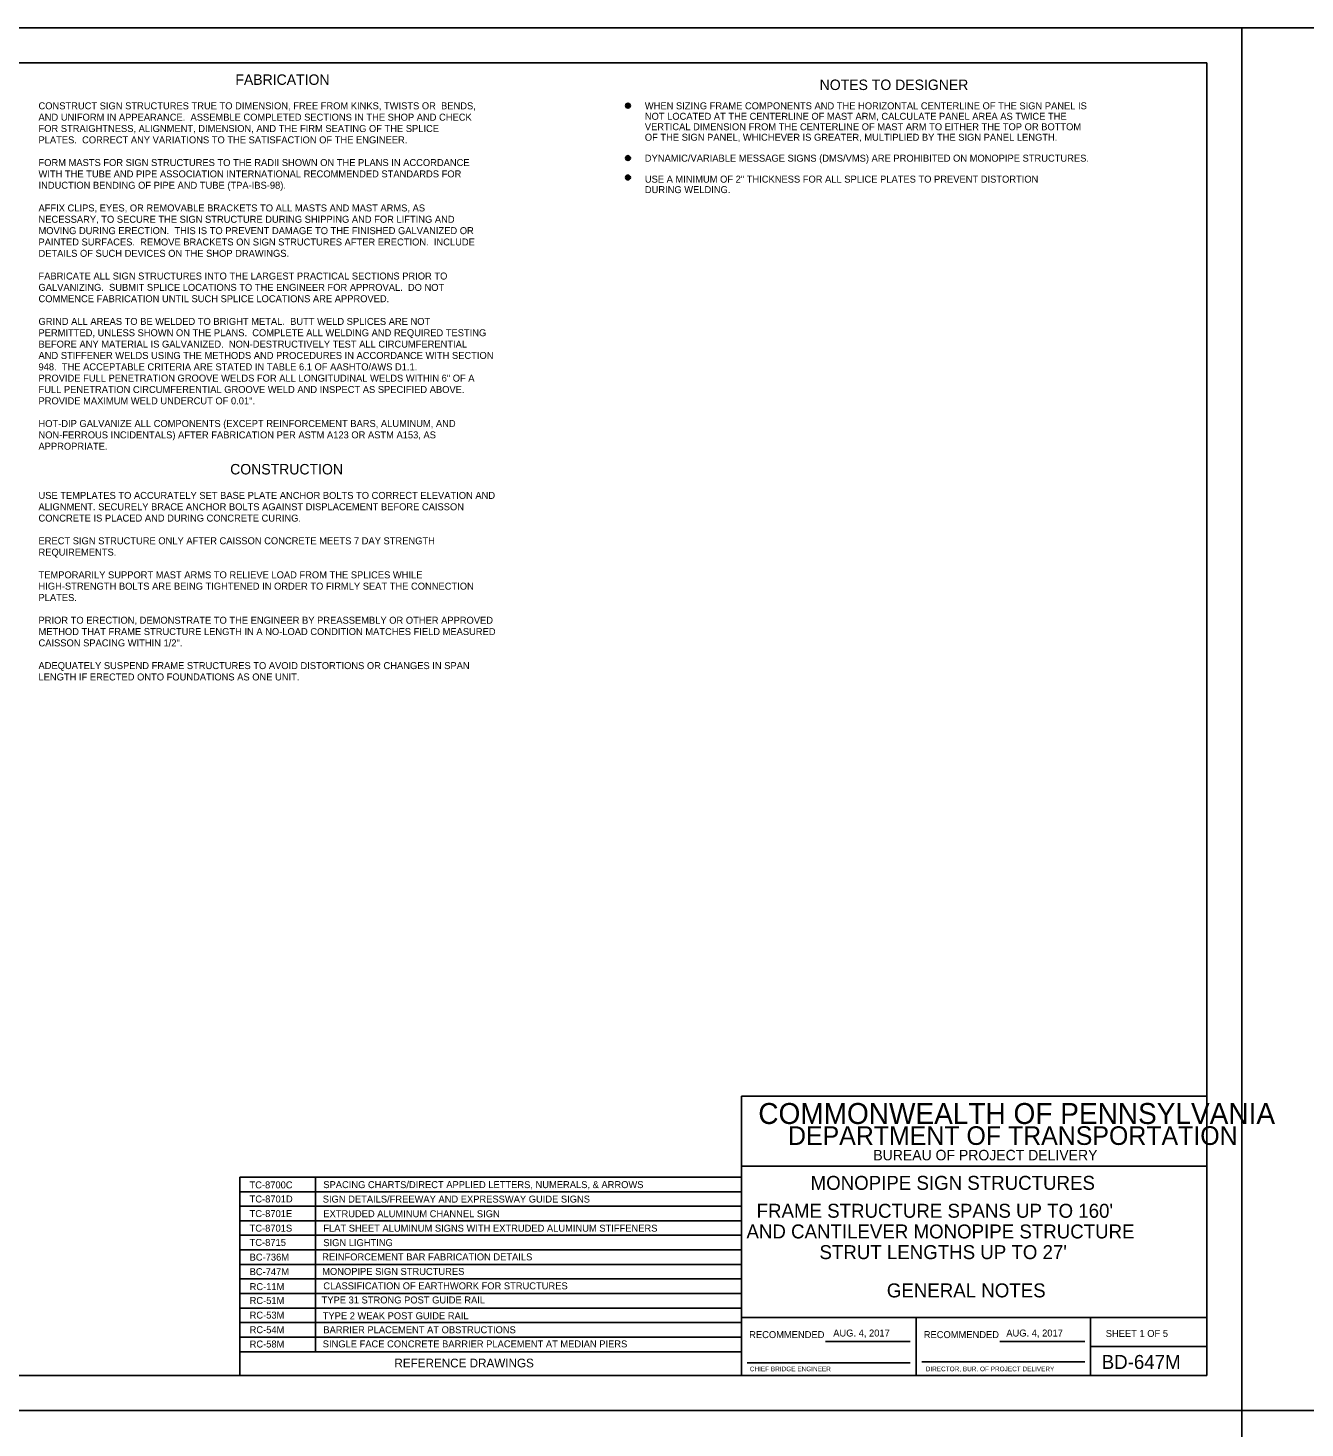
# Model space of a CAD drawing. Extents: x 640117 to 642655, y 297247 to 298435.
# Drawn here: x 640437 to 640986, y 297834 to 298435 of the extents above; entities that cross this region are included whole.
import ezdxf

# ---------------------------------------------------------------- set-up
doc = ezdxf.new("R2010")
doc.units = 0
for name, color, linetype in [('1', 7, 'Continuous'), ('10', 7, 'Continuous'), ('13', 7, 'Continuous'), ('2', 7, 'Continuous'), ('52', 7, 'Continuous'), ('53', 7, 'Continuous'), ('PLT-BNDY', 7, 'Continuous')]:
    doc.layers.add(name, color=color, linetype=linetype)

msp = doc.modelspace()

# ---------------------------------------------------------------- linework, layer by layer
at = {"layer": '1'}
for p, q in [((640818.46, 297856.46), (640818.46, 297881.46)), ((640779.54, 297871.17), (640815.96, 297871.17)), ((640854.54, 297871.17), (640890.96, 297871.17)), ((640745.96, 297861.96), (640815.96, 297861.96)), ((640820.96, 297862.33), (640890.96, 297862.33))]:
    msp.add_line(p, q, dxfattribs=at)
at = {"layer": '10'}
for centre, radius in [((640694.7, 298402.07), 1.04), ((640694.7, 298402.07), 0.781), ((640694.7, 298402.07), 0.521), ((640694.7, 298402.07), 0.26), ((640694.7, 298402.07), 0.00000208), ((640694.7, 298379.57), 1.04), ((640694.7, 298379.57), 0.781), ((640694.7, 298379.57), 0.521), ((640694.7, 298379.57), 0.26), ((640694.7, 298379.57), 0.00000208), ((640694.7, 298371.21), 1.04), ((640694.7, 298371.21), 0.781), ((640694.7, 298371.21), 0.521), ((640694.7, 298371.21), 0.26), ((640694.7, 298371.21), 0.00000208)]:
    msp.add_circle(centre, radius, dxfattribs=at)
at = {"layer": '13'}
for p, q in [((640528, 297856.46), (640528, 297941.74)), ((640528, 297941.74), (640743.46, 297941.74)), ((640560.46, 297866.74), (640560.46, 297941.74)), ((640528, 297935.49), (640743.46, 297935.49)), ((640528, 297929.24), (640743.46, 297929.24)), ((640528, 297922.99), (640743.46, 297922.99)), ((640528, 297916.74), (640743.46, 297916.74)), ((640528, 297910.49), (640743.46, 297910.49)), ((640528, 297904.24), (640743.46, 297904.24)), ((640528, 297897.99), (640743.46, 297897.99)), ((640528, 297891.74), (640743.46, 297891.74)), ((640528, 297885.49), (640743.46, 297885.49)), ((640528, 297879.24), (640743.46, 297879.24)), ((640528, 297872.99), (640743.46, 297872.99)), ((640528, 297872.99), (640743.46, 297872.99)), ((640528, 297866.74), (640743.46, 297866.74))]:
    msp.add_line(p, q, dxfattribs=at)
at = {"layer": '2'}
for p, q in [((640157.46, 298420.46), (640943.46, 298420.46)), ((640943.46, 298420.46), (640943.46, 297856.46)), ((640943.46, 297976.46), (640743.46, 297976.46)), ((640743.46, 297976.46), (640743.46, 297856.46)), ((640943.46, 297856.46), (640943.46, 297976.46)), ((640943.46, 297946.46), (640743.46, 297946.46)), ((640943.46, 297881.46), (640743.46, 297881.46)), ((640893.46, 297881.46), (640893.46, 297856.46)), ((640893.46, 297868.96), (640943.46, 297868.96)), ((640943.46, 297856.46), (640157.46, 297856.46)), ((640743.46, 297856.46), (640943.46, 297856.46))]:
    msp.add_line(p, q, dxfattribs=at)
at = {"layer": 'PLT-BNDY'}
for points in [[(640117.46, 298435.46), (640958.46, 298435.46), (640958.46, 297841.46), (640117.46, 297841.46)], [(640958.46, 298435.46), (641799.46, 298435.46), (641799.46, 297841.46), (640958.46, 297841.46)], [(640117.46, 297841.46), (640958.46, 297841.46), (640958.46, 297247.46), (640117.46, 297247.46)], [(640958.46, 297841.46), (641799.46, 297841.46), (641799.46, 297247.46), (640958.46, 297247.46)]]:
    msp.add_lwpolyline(points, close=True, dxfattribs=at)

# ---------------------------------------------------------------- texts
at = {"layer": '1'}
for s, height, p in [('RECOMMENDED', 3, (640746.79, 297872.58)), ('RECOMMENDED', 3, (640821.79, 297872.58)), ('CHIEF BRIDGE ENGINEER', 2.0002, (640747.05, 297858.33)), ('DIRECTOR, BUR. OF PROJECT DELIVERY', 2.0002, (640822.63, 297858.33))]:
    msp.add_text(s, height=height, dxfattribs=at).set_placement(p)
at = {"layer": '10'}
for s, height, p in [('WHEN SIZING FRAME COMPONENTS AND THE HORIZONTAL CENTERLINE OF THE SIGN PANEL IS ', 3, (640701.96, 298400.52)), ('NOT LOCATED AT THE CENTERLINE OF MAST ARM, CALCULATE PANEL AREA AS TWICE THE ', 3, (640701.96, 298396.02)), ('VERTICAL DIMENSION FROM THE CENTERLINE OF MAST ARM TO EITHER THE TOP OR BOTTOM ', 3, (640701.96, 298391.52)), ('OF THE SIGN PANEL, WHICHEVER IS GREATER, MULTIPLIED BY THE SIGN PANEL LENGTH.', 3, (640701.96, 298387.02)), ('DYNAMIC/VARIABLE MESSAGE SIGNS (DMS/VMS) ARE PROHIBITED ON MONOPIPE STRUCTURES.', 3, (640701.96, 298378.02)), ('USE A MINIMUM OF 2" THICKNESS FOR ALL SPLICE PLATES TO PREVENT DISTORTION ', 3, (640701.96, 298369.02)), ('DURING WELDING. ', 3, (640701.96, 298364.52)), ('MONOPIPE SIGN STRUCTURES', 6, (640773.18, 297936.28)), ('TC-8700C', 3, (640532.11, 297936.9)), ('SPACING CHARTS/DIRECT APPLIED LETTERS, NUMERALS, & ARROWS', 3, (640563.83, 297937.02)), ('TC-8701D', 3, (640532.16, 297930.85)), ('SIGN DETAILS/FREEWAY AND EXPRESSWAY GUIDE SIGNS', 3, (640563.58, 297930.81)), ("FRAME STRUCTURE SPANS UP TO 160'", 6, (640749.98, 297924.28)), ('TC-8701E', 3, (640532.16, 297924.58)), ('EXTRUDED ALUMINUM CHANNEL SIGN', 3, (640563.83, 297924.51)), ('TC-8701S', 3, (640532.16, 297918.31)), ('FLAT SHEET ALUMINUM SIGNS WITH EXTRUDED ALUMINUM STIFFENERS', 3, (640563.83, 297918.3)), ('AND CANTILEVER MONOPIPE STRUCTURE', 6, (640745.61, 297915.4)), ('TC-8715', 3, (640532.16, 297912.19)), ('SIGN LIGHTING', 3, (640563.83, 297912.1)), ("STRUT LENGTHS UP TO 27'", 6, (640776.98, 297906.51)), ('BC-736M', 3, (640532.16, 297905.87)), ('REINFORCEMENT BAR FABRICATION DETAILS', 3, (640563.34, 297905.98)), ('BC-747M', 3, (640532.16, 297899.62)), ('MONOPIPE SIGN STRUCTURES', 3, (640563.34, 297899.73)), ('RC-11M', 3, (640532.16, 297893.2)), ('CLASSIFICATION OF EARTHWORK FOR STRUCTURES', 3, (640563.83, 297893.52)), ('GENERAL NOTES', 6, (640805.92, 297890.07)), ('RC-51M', 3, (640532.16, 297887.23)), ('TYPE 31 STRONG POST GUIDE RAIL', 3, (640563.09, 297887.46)), ('RC-53M', 3, (640532.16, 297880.96)), ('TYPE 2 WEAK POST GUIDE RAIL', 3, (640563.58, 297880.67)), ('RC-54M', 3, (640532.16, 297874.68)), ('BARRIER PLACEMENT AT OBSTRUCTIONS', 3, (640563.83, 297874.66)), ('RC-58M', 3, (640532.16, 297868.54)), ('SINGLE FACE CONCRETE BARRIER PLACEMENT AT MEDIAN PIERS', 3, (640563.58, 297868.59)), ('REFERENCE DRAWINGS', 3.75, (640594.37, 297859.99)), ('BD-647M', 6, (640898.25, 297859.33))]:
    msp.add_text(s, height=height, dxfattribs=at).set_placement(p)
at = {"layer": '2'}
for s, height, p in [('COMMONWEALTH OF PENNSYLVANIA', 9, (640750.71, 297964.58)), ('DEPARTMENT OF TRANSPORTATION', 8.0002, (640763.46, 297955.58)), ('BUREAU OF PROJECT DELIVERY', 4.5, (640800.12, 297948.96)), ('SHEET 1 OF 5', 3, (640899.97, 297873.08))]:
    msp.add_text(s, height=height, dxfattribs=at).set_placement(p)
at = {"layer": '52'}
for p in [(640782.89, 297873.25), (640857.25, 297873.25)]:
    msp.add_text('AUG. 4, 2017', height=3, dxfattribs=at).set_placement(p)
at = {"layer": '53'}
for s, height, p in [('FABRICATION', 4.5, (640526.04, 298411.02)), ('NOTES TO DESIGNER', 4.5, (640777.07, 298408.8)), ('AND UNIFORM IN APPEARANCE.  ASSEMBLE COMPLETED SECTIONS IN THE SHOP AND CHECK ', 3, (640441.46, 298395.64)), ('CONSTRUCT SIGN STRUCTURES TRUE TO DIMENSION, FREE FROM KINKS, TWISTS OR  BENDS, ', 3, (640441.46, 298400.52)), ('FOR STRAIGHTNESS, ALIGNMENT, DIMENSION, AND THE FIRM SEATING OF THE SPLICE ', 3, (640441.46, 298390.77)), ('PLATES.  CORRECT ANY VARIATIONS TO THE SATISFACTION OF THE ENGINEER.', 3, (640441.46, 298385.89)), ('WITH THE TUBE AND PIPE ASSOCIATION INTERNATIONAL RECOMMENDED STANDARDS FOR ', 3, (640441.46, 298371.27)), ('FORM MASTS FOR SIGN STRUCTURES TO THE RADII SHOWN ON THE PLANS IN ACCORDANCE  ', 3, (640441.46, 298376.14)), ('INDUCTION BENDING OF PIPE AND TUBE (TPA-IBS-98).', 3, (640441.46, 298366.39)), ('AFFIX CLIPS, EYES, OR REMOVABLE BRACKETS TO ALL MASTS AND MAST ARMS, AS  ', 3, (640441.46, 298356.64)), ('NECESSARY, TO SECURE THE SIGN STRUCTURE DURING SHIPPING AND FOR LIFTING AND ', 3, (640441.46, 298351.77)), ('MOVING DURING ERECTION.  THIS IS TO PREVENT DAMAGE TO THE FINISHED GALVANIZED OR ', 3, (640441.46, 298346.89)), ('PAINTED SURFACES.  REMOVE BRACKETS ON SIGN STRUCTURES AFTER ERECTION.  INCLUDE ', 3, (640441.46, 298342.02)), ('DETAILS OF SUCH DEVICES ON THE SHOP DRAWINGS.', 3, (640441.46, 298337.14)), ('FABRICATE ALL SIGN STRUCTURES INTO THE LARGEST PRACTICAL SECTIONS PRIOR TO  ', 3, (640441.46, 298327.39)), ('GALVANIZING.  SUBMIT SPLICE LOCATIONS TO THE ENGINEER FOR APPROVAL.  DO NOT ', 3, (640441.46, 298322.52)), ('COMMENCE FABRICATION UNTIL SUCH SPLICE LOCATIONS ARE APPROVED.', 3, (640441.46, 298317.64)), ('GRIND ALL AREAS TO BE WELDED TO BRIGHT METAL.  BUTT WELD SPLICES ARE NOT  ', 3, (640441.46, 298307.89)), ('PERMITTED, UNLESS SHOWN ON THE PLANS.  COMPLETE ALL WELDING AND REQUIRED TESTING ', 3, (640441.46, 298303.02)), ('AND STIFFENER WELDS USING THE METHODS AND PROCEDURES IN ACCORDANCE WITH SECTION ', 3, (640441.46, 298293.27)), ('BEFORE ANY MATERIAL IS GALVANIZED.  NON-DESTRUCTIVELY TEST ALL CIRCUMFERENTIAL ', 3, (640441.46, 298298.14)), ('948.  THE ACCEPTABLE CRITERIA ARE STATED IN TABLE 6.1 OF AASHTO/AWS D1.1. ', 3, (640441.46, 298288.39)), ('PROVIDE FULL PENETRATION GROOVE WELDS FOR ALL LONGITUDINAL WELDS WITHIN 6" OF A ', 3, (640441.46, 298283.52)), ('FULL PENETRATION CIRCUMFERENTIAL GROOVE WELD AND INSPECT AS SPECIFIED ABOVE.  ', 3, (640441.46, 298278.64)), ('PROVIDE MAXIMUM WELD UNDERCUT OF 0.01".', 3, (640441.46, 298273.77)), ('HOT-DIP GALVANIZE ALL COMPONENTS (EXCEPT REINFORCEMENT BARS, ALUMINUM, AND  ', 3, (640441.46, 298264.02)), ('NON-FERROUS INCIDENTALS) AFTER FABRICATION PER ASTM A123 OR ASTM A153, AS ', 3, (640441.46, 298259.14)), ('APPROPRIATE.', 3, (640441.46, 298254.27)), ('CONSTRUCTION', 4.5, (640523.81, 298243.64)), ('USE TEMPLATES TO ACCURATELY SET BASE PLATE ANCHOR BOLTS TO CORRECT ELEVATION AND ', 3, (640441.46, 298233.14)), ('ALIGNMENT. SECURELY BRACE ANCHOR BOLTS AGAINST DISPLACEMENT BEFORE CAISSON ', 3, (640441.46, 298228.26)), ('CONCRETE IS PLACED AND DURING CONCRETE CURING.', 3, (640441.46, 298223.39)), ('ERECT SIGN STRUCTURE ONLY AFTER CAISSON CONCRETE MEETS 7 DAY STRENGTH ', 3, (640441.46, 298213.64)), ('REQUIREMENTS.', 3, (640441.46, 298208.76)), ('TEMPORARILY SUPPORT MAST ARMS TO RELIEVE LOAD FROM THE SPLICES WHILE ', 3, (640441.46, 298199.01)), ('HIGH-STRENGTH BOLTS ARE BEING TIGHTENED IN ORDER TO FIRMLY SEAT THE CONNECTION ', 3, (640441.46, 298194.14)), ('PLATES.', 3, (640441.46, 298189.26)), ('PRIOR TO ERECTION, DEMONSTRATE TO THE ENGINEER BY PREASSEMBLY OR OTHER APPROVED ', 3, (640441.46, 298179.51)), ('METHOD THAT FRAME STRUCTURE LENGTH IN A NO-LOAD CONDITION MATCHES FIELD MEASURED ', 3, (640441.46, 298174.64)), ('CAISSON SPACING WITHIN 1/2".', 3, (640441.46, 298169.76)), ('ADEQUATELY SUSPEND FRAME STRUCTURES TO AVOID DISTORTIONS OR CHANGES IN SPAN ', 3, (640441.46, 298160.01)), ('LENGTH IF ERECTED ONTO FOUNDATIONS AS ONE UNIT.', 3, (640441.46, 298155.14))]:
    msp.add_text(s, height=height, dxfattribs=at).set_placement(p)

doc.saveas('drawing.dxf')
